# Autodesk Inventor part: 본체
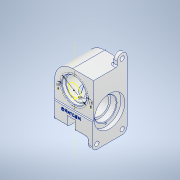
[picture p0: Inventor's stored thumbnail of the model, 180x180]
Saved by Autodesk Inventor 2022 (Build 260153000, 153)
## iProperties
Created: 2023-09
Part Number: 본체
Material: 알루미늄 6061
Document SubType Name: Modeling
Designer: PC-13
Density: 2.7 g/cm^3
Appearance: 알루미늄 - 평지
Mass: 944.108 g
Surface Area: 630.513 cm^2
Volume: 349.669 cm^3
Author: PC-13
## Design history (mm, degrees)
sketch "스케치1"
  geometry: L1 (-56, 0)-(56, 0) reference; L2 (0, -74.2)-(0, 74.2) reference; L3 (-40, 53)-(-40, -53); L4 (-40, -53)-(40, -53); L5 (40, -53)-(40, 53); L6 (40, 53)-(-40, 53); 1 further point
  constraints: 8 end point, 3 perpendicular, 1 vertical, 2 other
  dimensions: "d0" = 80 distance of L5.end L3.start; "d1" = 106 distance of L3.start L3.end
extrude "돌출1" new body sketch "스케치1" stored distance "d2" = 72; taper "d3" = 0 deg
fillet "모깎기1" dims "d4" = 37
sketch "스케치2"
  geometry: L1 (0, -74.2)-(0, 74.2) reference; L2 (-56, 0)-(56, 0) reference; L3 (40, -53)-(40, 53) reference; L4 (40, -53)-(40, -73); L5 (40, -73)-(30, -73); L6 (30, -73)-(30, -53); L7 (-40, -53)-(40, -53) reference; L8 (30, -53)-(40, -53); 1 further point
  constraints: 8 end point, 2 perpendicular, 1 collinear, 1 point on line, 1 vertical
  dimensions: "d5" = 10 distance of L4.end L5.end; "d6" = 20 distance of L3.start L4.end
extrude "돌출2" join sketch "스케치2" distance "d7" = 72; taper "d8" = 0 deg
sketch "스케치3"
  geometry: L1 (86.4, -53)-(-14.4, -53) reference; L2 (36, -155.2)-(36, 49.2) reference; L3 (72, 0)-(0, 0) reference; L4 (72, 0)-(72, 20); L5 (72, 20)-(52, 20); L6 (52, 20)-(52, 0); L7 (52, 0)-(72, 0); 1 further point
  constraints: 8 end point, 2 perpendicular, 1 collinear, 1 point on line, 1 vertical
  dimensions: "d9" = 20 distance of L4.end L5.end; "d10" = 20 distance of L3.start L4.end
extrude "돌출3" join sketch "스케치3" distance "d11" = 10; taper "d12" = 0 deg
sketch "스케치4"
  geometry: L1 (36, -29.2)-(36, 175.2) reference; L2 (86.4, 73)-(-14.4, 73) reference; L3 (0, 0)-(0, 126) reference; L4 (0, 126)-(3, 126); L5 (52, 126)-(0, 126) reference; L6 (3, 126)-(3, 54); L7 (3, 54)-(0, 54); L8 (0, 54)-(0, 126); 2 further points
  constraints: 8 end point, 3 perpendicular, 1 point on line
  dimensions: "d13" = 3 distance of L3.end L4.end; "d14" = 72 distance of L4.end L6.end
extrude "돌출4" cut sketch "스케치4" distance "d15" = 80; taper "d16" = 0 deg
fillet "모깎기2" dims "d17" = 10
fillet "모깎기3" dims "d18" = 10
sketch "스케치5"
  geometry: A1 r 10 centre (-62, 10) between (-52, 10) and (-72, 10) reference; 2 further points
  constraints: 1 coincident
hole "구멍1" sketch "스케치5" at (-62, 10) diameter "d19" = 9; stored, may be unused: countersink angle "d23" = 90 deg, drill point angle "d25" = 118 deg; dims "d20" = 6, "d21" = 4, "d22" = 2, "d24" = 8
sketch "스케치6"
  geometry: A1 r 10 centre (10, -10) between (0, -10) and (10, -20) reference; 2 further points
  constraints: 1 coincident
hole "구멍2" sketch "스케치6" at (10, -10) diameter "d26" = 9; stored, may be unused: countersink angle "d30" = 90 deg, drill point angle "d32" = 118 deg; dims "d27" = 6, "d28" = 4, "d29" = 2, "d31" = 8
sketch "스케치7"
  geometry: A1 r 10 centre (62, -10) between (62, -20) and (72, -10) reference; 2 further points
  constraints: 1 coincident
hole "구멍3" sketch "스케치7" at (62, -10) diameter "d33" = 9; stored, may be unused: countersink angle "d37" = 90 deg, drill point angle "d39" = 118 deg; dims "d34" = 6, "d35" = 4, "d36" = 2, "d38" = 8
sketch "스케치8"
  geometry: L1 (-56, 0)-(56, 0) reference; L2 (0, -102.2)-(0, 102.2) reference; L3 (30, -53)-(-40, -53) reference; L4 (-11, -53)-(-11, -33); L5 (-11, -33)-(5, -33); L6 (5, -33)-(5, -53); L7 (-11, -53)-(5, -53); L8 (40, -63)-(40, -19) reference; 1 further point
  constraints: 8 end point, 2 perpendicular, 2 point on line, 1 collinear, 1 vertical
  dimensions: "d40" = 16 distance of L4.end L5.end; "d41" = 20 distance of L5.end L6.end; "d42" = 51 distance between parallel lines of L4 L8
extrude "돌출5" cut sketch "스케치8" distance "d43" = 72; taper "d44" = 0 deg
sketch "스케치9"
  geometry: L1 (0, -50.4)-(0, 50.4) reference; L2 (-102.2, 0)-(102.2, 0) reference; L3 (16, 45.509)-(16, -53.175); L4 (-53, -36)-(-53, 36) reference; L5 (16, 33)-(53, 33) reference; L6 (41, 33)-(41, 26); L7 (41, 26)-(39, 26); L8 (39, 26)-(39, -14); L9 (39, -14)-(34.5, -14); L10 (33.5, -15)-(33.5, -28.7); L11 (33.2, -29)-(31.5, -29); L12 (31.5, -29)-(31.5, -30); L13 (28.5, -33)-(16, -33); L14 (16, -36)-(16, 33) reference; L15 (41, 33)-(16, 33); L16 (34.5, -14)-(33.5, -15); A1 r 3 centre (28.5, -30) between (28.5, -33) and (31.5, -30); A2 r 0.3 centre (33.2, -28.7) between (33.2, -29) and (33.5, -28.7); 5 further points
  constraints: 22 end point, 9 perpendicular, 8 point on line, 4 point on circle, 4 tangent, 2 centre point, 1 vertical
  dimensions: "d45" = 69 distance between parallel lines of L3 L4; "d46" = 50 diameter of L6 L3; "d47" = 46 diameter of L8 L3; "d48" = 35 diameter of L10 L3; "d49" = 31 diameter of L12 L3; "d50" = 7 distance of L6.start L6.end; "d51" = 40 distance of L7.end L8.end; "d52" = 15 distance of point (33.5, -14) point (33.5, -29); "d53" = 4 distance of L11.end point (31.5, -33); "d54" = 3 radius of A1; "d55" = 0.3 radius of A2; "d56" = 1 distance of L9.end point (33.5, -14); "d57" = 1 distance of L10.start point (33.5, -14) (= d56)
revolve "회전1" sketch "스케치9" stored, may be unused: angle "d58" = 90 deg
chamfer "모따기1" distance "d59" = 1; stored, may be unused: second distance "d60" = 2, angle "d61" = 45 deg
sketch "스케치11"
  geometry: L1 (-61.984, -18)-(81.394, -18); L2 (-11, -53)-(-40, -53) reference; L3 (-25, -40.5)-(-25, -36.5); L4 (-25, -36.5)-(20, -36.5); L5 (20, -36.5)-(20, -40.5); L6 (20, -40.5)-(31, -40.5); L7 (32, -41.5)-(32, -49.5); L8 (32, -49.5)-(40, -49.5); L9 (40, -63)-(40, 63) reference; L10 (-25, -40.5)-(-36, -40.5); L11 (-37, -41.5)-(-37, -49.5); L12 (-37, -49.5)-(-40, -49.5); L13 (-40, -53)-(-40, 16) reference; L14 (-40, -49.5)-(-40, -18.5); L15 (40, -49.5)-(40, -18); L16 (-37, -41.5)-(-36, -40.5); L17 (32, -41.5)-(31, -40.5); 4 further points
  constraints: 28 end point, 8 point on line, 5 perpendicular, 4 horizontal, 1 midpoint
  dimensions: "d62" = 35 distance between parallel lines of L1 L2; "d63" = 3 distance of L11.end L12.end; "d64" = 12 distance of L3.start point (-37, -40.5); "d65" = 12 distance of L5.end point (32, -40.5); "d66" = 8 distance of L7.end L8.end; "d68" = 63 diameter of L12 L1; "d69" = 45 diameter of L10 L1; "d70" = 37 diameter of L4 L1; "d71" = 45 diameter of L6 L1; "d72" = 63 diameter of L8 L1; "d73" = 1 distance of L11.start point (-37, -40.5); "d74" = 1 distance of L10.end point (-37, -40.5) (= d73); "d75" = 1 distance of L7.start point (32, -40.5) (= d73); "d76" = 1 distance of L6.end point (32, -40.5) (= d75)
revolve "회전2" sketch "스케치11" stored, may be unused: angle "d77" = 90 deg
fillet "모깎기4" dims "d78" = 3
fillet "모깎기5" dims "d79" = 3
fillet "모깎기6" dims "d80" = 3
sketch "스케치13"
  geometry: L1 (-37, -53)-(-11, -53) reference; L2 (40, -63)-(40, -19) reference; 2 further points
  constraints: 1 other
  dimensions: "d81" = 27 distance from line of L1 point (-3, -26); "d82" = 43 distance from line of L2 point (-3, -26)
feature "엠보싱1" sketch "스케치13" dims "d8" = 0, "d83" = 0.5, "d84" = 0
sketch "스케치14"
  geometry: L1 (0, -84.2)-(0, 120.2) reference; L2 (-50.5, 18)-(51, 18) reference; C1 r 22.5 at (0, 0) reference; A1 r 26 centre (0, 0) between (0, 26) and (0, -26); 1 further point
  constraints: 2 point on circle, 1 centre point, 1 coincident
  dimensions: "d86" = 52 diameter of A1; "d87" = 8 distance from line of L2 A1.start; "d88" = 44 distance from line of L2 A1.end
hole "구멍4" sketch "스케치14" at (0, 26), (0, -26) diameter "d89" = 3.242; stored, may be unused: countersink angle "d93" = 90 deg, drill point angle "d95" = 118 deg; dims "d90" = 8, "d91" = 4, "d92" = 2, "d94" = 10
sketch "스케치15"
  geometry: L1 (60.501, 18)-(-111.006, 18) reference; L2 (0, -84.2)-(0, 120.2) reference; A1 r 26 centre (0, 0) between (0, 26) and (0, -26); 1 further point
  constraints: 3 point on line, 2 point on circle, 1 centre point
  dimensions: "d96" = 52 diameter of A1; "d97" = 18 distance from line of L1 A1.centre
hole "구멍5" sketch "스케치15" at (0, 26), (0, -26) diameter "d98" = 3.242; stored, may be unused: countersink angle "d102" = 90 deg, drill point angle "d104" = 118 deg; dims "d99" = 8, "d100" = 4, "d101" = 2, "d103" = 10
sketch "스케치16"
  geometry: L1 (-96, 19)-(16, 19) reference; L2 (-40, -83.2)-(-40, 121.2) reference; C1 r 12.5 at (-40, 35) reference; A1 r 29 centre (-40, 35) between (-40, 64) and (-40, 6); 3 further points
  constraints: 4 point on circle, 2 point on line, 1 centre point, 1 coincident
  dimensions: "d105" = 58 diameter of A1; "d124" = 16 distance from line of L1 point (-11, 35); "d125" = 16 distance from line of L1 point (-69, 35)
sketch "스케치17"
  geometry: L1 (-26, -72)-(0, -72) reference; L2 (16, -3)-(16, -69) reference; 3 further points
  dimensions: "d113" = 50 distance of point (8, -61) point (8, -11); "d114" = 11 distance from line of L1 point (8, -61); "d115" = 8 distance from line of point (8, -11) L2; "d116" = 8 distance from line of L2 point (8, -61)
hole "구멍7" sketch "스케치17" at (8, -11), (8, -61) diameter "d117" = 3.242; stored, may be unused: countersink angle "d121" = 90 deg, drill point angle "d123" = 118 deg; dims "d118" = 8, "d119" = 4, "d120" = 2, "d122" = 10
hole "구멍8" sketch "스케치16" diameter "d126" = 3.242; stored, may be unused: countersink angle "d130" = 90 deg, drill point angle "d132" = 118 deg; dims "d127" = 8, "d128" = 4, "d129" = 2, "d131" = 10
node "솔리드1"
feature "A9D066F2-1C7D-4E18-AEED-F7BC21143FA4" dims "d19" = 9, "d20" = 6, "d21" = 4, "d22" = 2, "d23" = 90 deg, "d24" = 8, "d25" = 118 deg
